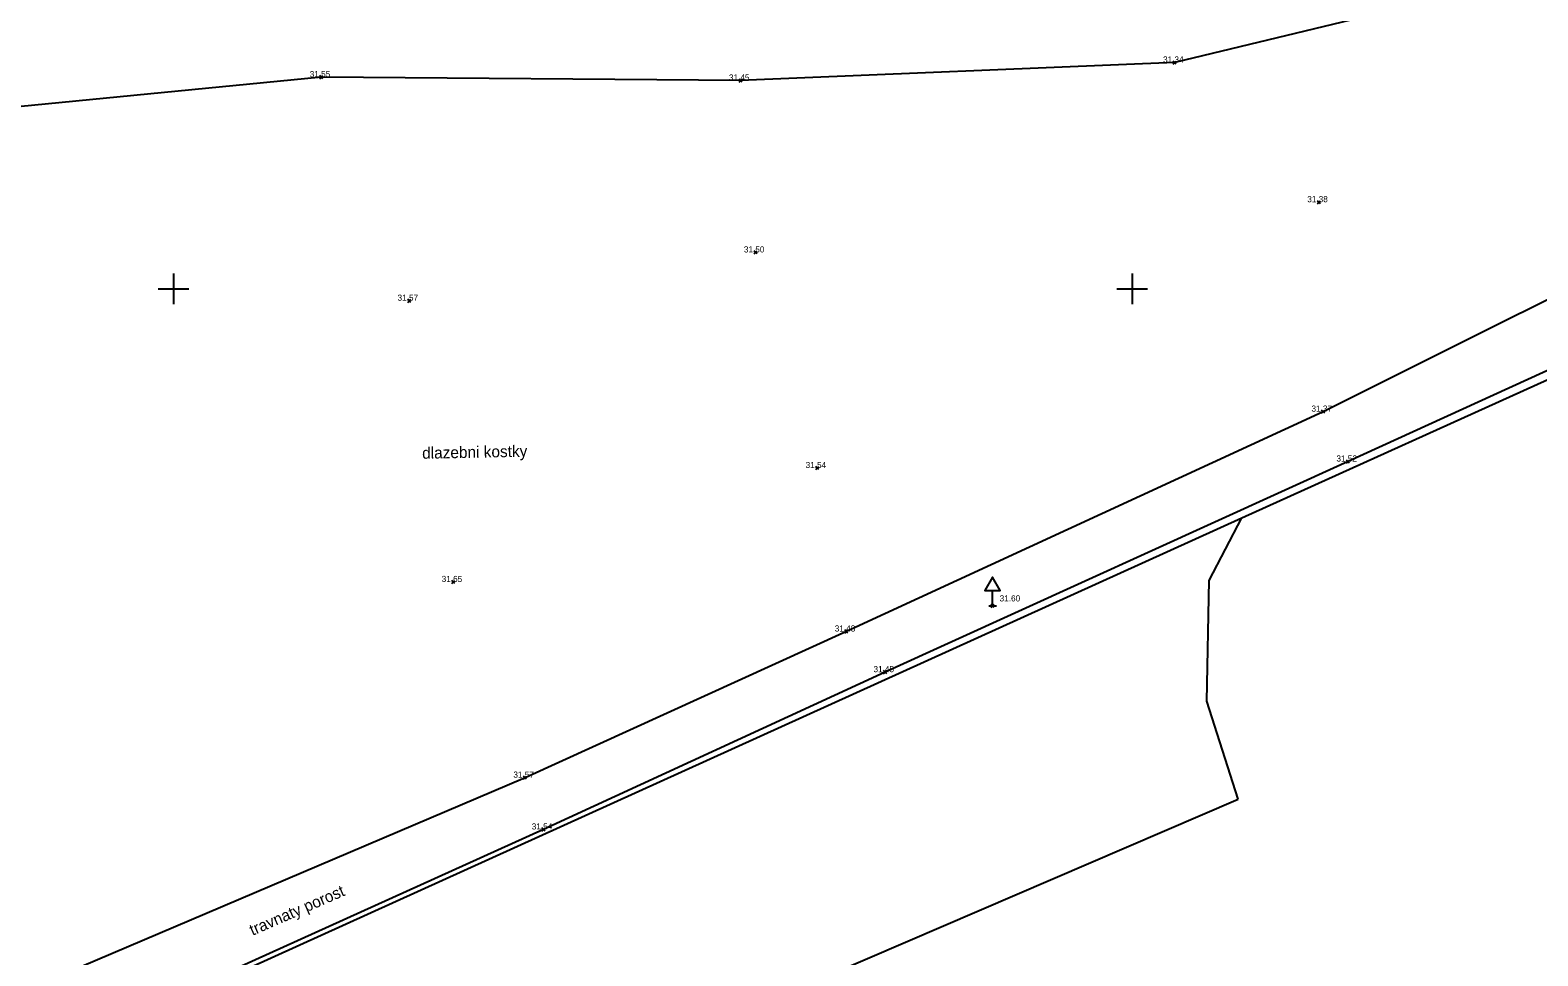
# Model space of a CAD drawing. Extents: x -772865 to -772533, y -1034366 to -1034132.
# Drawn here: x -772628.73 to -772589.42, y -1034242.38 to -1034218.26 of the extents above; entities that cross this region are included whole.
import ezdxf

# ---------------------------------------------------------------- set-up
doc = ezdxf.new("R2010")
doc.units = 0
for name, color, linetype in [('body', 7, 'Continuous'), ('dopravni_znacky', 7, 'Continuous'), ('KM_hranice', 7, 'Continuous'), ('mistni_popis', 7, 'Continuous'), ('oddeleni_ploch', 7, 'Continuous'), ('oploceni', 7, 'Continuous'), ('souradnicova_sit', 7, 'Continuous'), ('vyskove_koty', 7, 'Continuous')]:
    doc.layers.add(name, color=color, linetype=linetype)

msp = doc.modelspace()

# ---------------------------------------------------------------- linework, layer by layer
at = {"layer": 'body'}
for p, q in [((-772598.85, -1034219.14), (-772598.93, -1034219.06)), ((-772598.93, -1034219.14), (-772598.85, -1034219.06)), ((-772621.1, -1034219.52), (-772621.18, -1034219.44)), ((-772621.18, -1034219.52), (-772621.1, -1034219.44)), ((-772610.17, -1034219.61), (-772610.25, -1034219.53)), ((-772610.25, -1034219.61), (-772610.17, -1034219.53)), ((-772595.09, -1034222.78), (-772595.17, -1034222.7)), ((-772595.17, -1034222.78), (-772595.09, -1034222.7)), ((-772609.78, -1034224.09), (-772609.86, -1034224.01)), ((-772609.86, -1034224.09), (-772609.78, -1034224.01)), ((-772618.81, -1034225.35), (-772618.89, -1034225.27)), ((-772618.89, -1034225.35), (-772618.81, -1034225.27)), ((-772594.98, -1034228.24), (-772595.06, -1034228.16)), ((-772595.06, -1034228.24), (-772594.98, -1034228.16)), ((-772594.33, -1034229.54), (-772594.41, -1034229.46)), ((-772594.41, -1034229.54), (-772594.33, -1034229.46)), ((-772608.17, -1034229.71), (-772608.25, -1034229.63)), ((-772608.25, -1034229.71), (-772608.17, -1034229.63)), ((-772617.66, -1034232.68), (-772617.74, -1034232.6)), ((-772617.74, -1034232.68), (-772617.66, -1034232.6)), ((-772603.6, -1034233.3), (-772603.68, -1034233.22)), ((-772603.68, -1034233.3), (-772603.6, -1034233.22)), ((-772607.41, -1034233.97), (-772607.49, -1034233.89)), ((-772607.49, -1034233.97), (-772607.41, -1034233.89)), ((-772606.4, -1034235.03), (-772606.48, -1034234.95)), ((-772606.48, -1034235.03), (-772606.4, -1034234.95)), ((-772615.79, -1034237.78), (-772615.87, -1034237.7)), ((-772615.87, -1034237.78), (-772615.79, -1034237.7)), ((-772615.31, -1034239.13), (-772615.39, -1034239.05)), ((-772615.39, -1034239.13), (-772615.31, -1034239.05))]:
    msp.add_line(p, q, dxfattribs=at)
at = {"layer": 'dopravni_znacky'}
msp.add_line((-772603.74, -1034233.26), (-772603.54, -1034233.26), dxfattribs=at)
msp.add_lwpolyline([(-772603.64, -1034233.26), (-772603.64, -1034232.86), (-772603.44, -1034232.86), (-772603.64, -1034232.51), (-772603.84, -1034232.86), (-772603.64, -1034232.86)], dxfattribs=at)
at = {"layer": 'KM_hranice'}
for p, q in [((-772597.14, -1034230.97), (-772580.4, -1034223.39)), ((-772677.97, -1034267.58), (-772597.14, -1034230.97)), ((-772597.99, -1034232.6), (-772597.14, -1034230.97)), ((-772598.05, -1034235.75), (-772597.99, -1034232.6)), ((-772597.24, -1034238.3), (-772598.05, -1034235.75)), ((-772611.14, -1034244.27), (-772597.24, -1034238.3))]:
    msp.add_line(p, q, dxfattribs=at)
at = {"layer": 'oddeleni_ploch'}
for points in [[(-772569.67, -1034207.72), (-772578.35, -1034211.18), (-772588.33, -1034216.15), (-772592.11, -1034217.46), (-772598.89, -1034219.1), (-772610.21, -1034219.57), (-772621.14, -1034219.48), (-772637.34, -1034221.06), (-772647.54, -1034222.08), (-772674.34, -1034233.24), (-772685.01, -1034239.21), (-772697.33, -1034242.95), (-772712.12, -1034249.56), (-772725.85, -1034254.8), (-772738.85, -1034261.98), (-772750.37, -1034267.76), (-772764, -1034272.65), (-772783.9, -1034280.59), (-772796.38, -1034286.28), (-772810.31, -1034291.67), (-772823.61, -1034294.35), (-772828.52, -1034296.12), (-772827.01, -1034302.81), (-772823.23, -1034300.75)], [(-772567.34, -1034212.16), (-772571.18, -1034215.04), (-772571.09, -1034215.8), (-772573.98, -1034216.98), (-772577.45, -1034219.11), (-772584.7, -1034223.05), (-772595.02, -1034228.2), (-772607.45, -1034233.93), (-772615.83, -1034237.74), (-772627.86, -1034242.86), (-772647.89, -1034252.03), (-772658, -1034256.56), (-772672.84, -1034263.1), (-772676.49, -1034257.87), (-772679.65, -1034256.43), (-772682.64, -1034256.79), (-772689.63, -1034259.88), (-772704.53, -1034266.45)]]:
    msp.add_lwpolyline(points, dxfattribs=at)
at = {"layer": 'oploceni'}
msp.add_lwpolyline([(-772580.41, -1034223.13), (-772594.37, -1034229.5), (-772606.44, -1034234.99), (-772615.35, -1034239.09), (-772626.89, -1034244.31), (-772647.29, -1034253.6), (-772657.19, -1034258.12), (-772675.87, -1034266.57), (-772700.9, -1034277.76), (-772711.36, -1034282.37), (-772727.94, -1034289.85)], dxfattribs=at)
at = {"layer": 'souradnicova_sit'}
for p, q in [((-772625, -1034224.6), (-772625, -1034225.4)), ((-772600, -1034224.6), (-772600, -1034225.4)), ((-772625.4, -1034225), (-772624.6, -1034225)), ((-772600.4, -1034225), (-772599.6, -1034225))]:
    msp.add_line(p, q, dxfattribs=at)

# ---------------------------------------------------------------- texts
at = {"layer": 'mistni_popis'}
for s, rotation, p in [('dlazebni kostky', 1.1459, (-772618.511, -1034229.428)), ('travnaty porost', 23.5486, (-772622.937, -1034241.863))]:
    msp.add_text(s, height=0.3, rotation=rotation, dxfattribs=at).set_placement(p)
at = {"layer": 'vyskove_koty'}
for s, p in [('31.34', (-772599.195, -1034219.1)), ('31.55', (-772621.445, -1034219.48)), ('31.45', (-772610.515, -1034219.57)), ('31.38', (-772595.435, -1034222.74)), ('31.50', (-772610.125, -1034224.05)), ('31.57', (-772619.155, -1034225.31)), ('31.37', (-772595.325, -1034228.2)), ('31.54', (-772608.515, -1034229.67)), ('31.52', (-772594.675, -1034229.5)), ('31.65', (-772618.005, -1034232.64)), ('31.60', (-772603.456, -1034233.146)), ('31.48', (-772607.755, -1034233.93)), ('31.45', (-772606.745, -1034234.99)), ('31.57', (-772616.135, -1034237.74)), ('31.54', (-772615.655, -1034239.09))]:
    msp.add_text(s, height=0.16, dxfattribs=at).set_placement(p)

doc.saveas('drawing.dxf')
